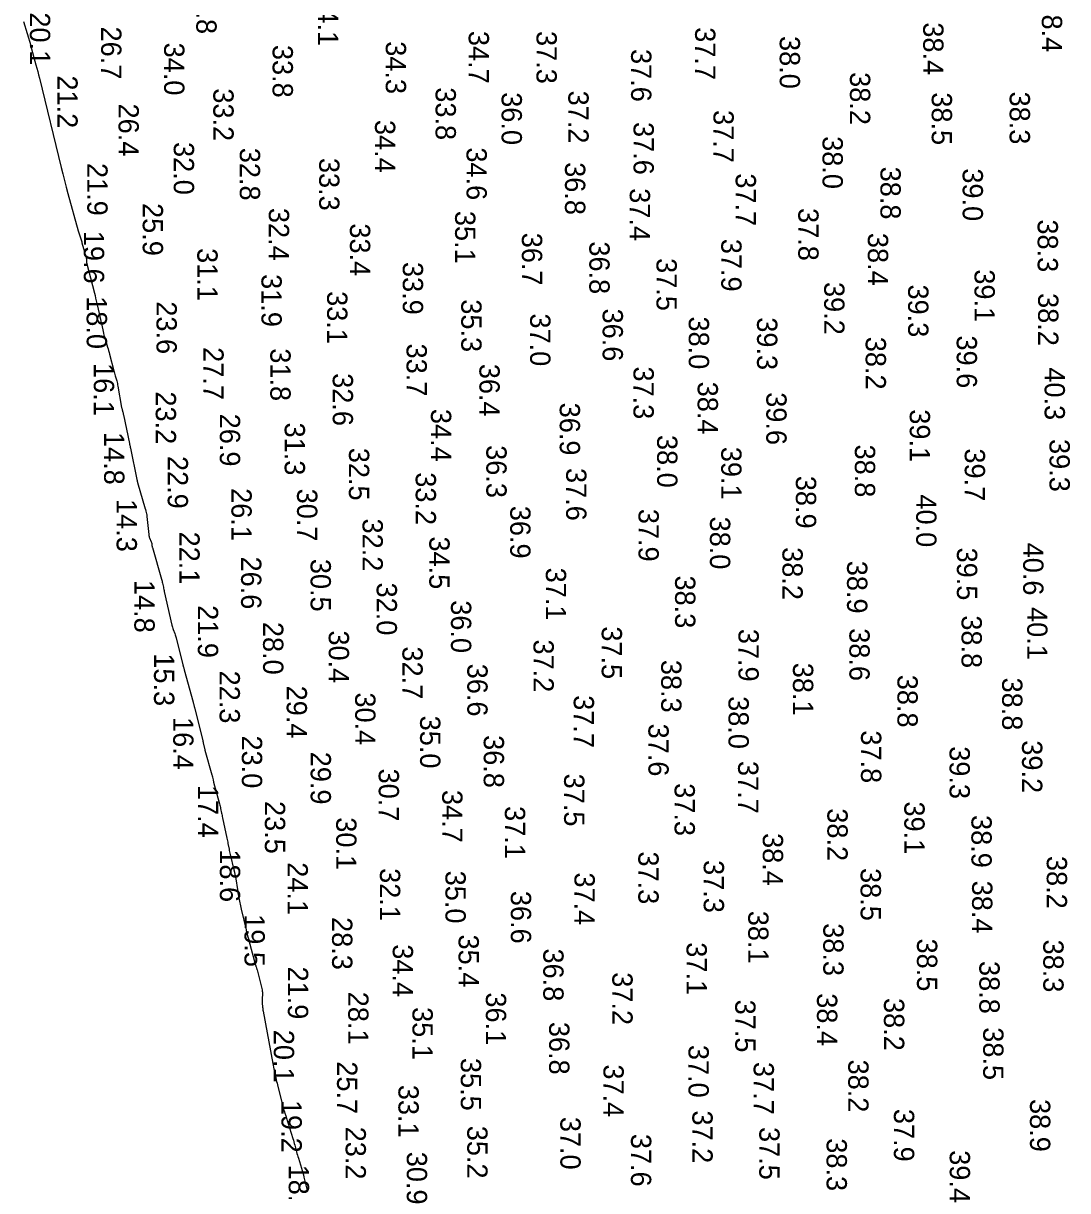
# Model space of a CAD drawing. Extents: x 1178573 to 1187098, y 693282 to 751751.
# Drawn here: x 1180394 to 1181038, y 701736 to 702455 of the extents above; entities that cross this region are included whole.
import ezdxf

# ---------------------------------------------------------------- set-up
doc = ezdxf.new("R2010")
doc.units = 0
doc.layers.add('V-HYDS-MINR', color=7, linetype='Continuous')
doc.layers.add('V-HYDS-SOUN', color=7, linetype='Continuous')

msp = doc.modelspace()

# ---------------------------------------------------------------- linework, layer by layer
at = {"layer": 'V-HYDS-MINR'}
msp.add_lwpolyline([(1180394.31, 702455.91), (1180398.97, 702440.99), (1180398.99, 702440.92), (1180398.99, 702440.89), (1180398.96, 702440.9), (1180398.91, 702440.95), (1180398.68, 702441.24), (1180398.63, 702441.29), (1180398.61, 702441.31), (1180398.6, 702441.28), (1180398.62, 702441.21), (1180402.02, 702429.11), (1180402.59, 702427.06), (1180403.14, 702425), (1180403.67, 702422.95), (1180404.18, 702420.88), (1180417.59, 702365.99), (1180418.6, 702361.93), (1180419.63, 702357.88), (1180420.7, 702353.84), (1180421.79, 702349.81), (1180428.09, 702326.87), (1180428.26, 702326.25), (1180428.45, 702325.64), (1180428.64, 702325.03), (1180428.85, 702324.42), (1180429.69, 702322), (1180429.89, 702321.39), (1180430.08, 702320.78), (1180430.26, 702320.17), (1180430.43, 702319.55), (1180431.9, 702313.95), (1180432, 702313.56), (1180432.12, 702313.17), (1180432.24, 702312.79), (1180432.36, 702312.4), (1180432.96, 702310.62), (1180433.04, 702310.36), (1180433.1, 702310.09), (1180433.13, 702309.82), (1180433.15, 702309.55), (1180433.17, 702308.44), (1180433.18, 702308.17), (1180433.21, 702307.89), (1180433.25, 702307.62), (1180433.31, 702307.36), (1180438.05, 702288.6), (1180438.45, 702287), (1180438.84, 702285.39), (1180439.22, 702283.77), (1180439.6, 702282.16), (1180441.19, 702275.19), (1180441.5, 702273.83), (1180441.8, 702272.47), (1180442.1, 702271.11), (1180442.39, 702269.75), (1180443.68, 702263.76), (1180443.93, 702262.68), (1180444.21, 702261.6), (1180444.51, 702260.52), (1180444.84, 702259.46), (1180446.21, 702255.21), (1180446.54, 702254.15), (1180446.86, 702253.08), (1180447.16, 702252), (1180447.44, 702250.92), (1180450.04, 702240.74), (1180450.25, 702239.95), (1180450.46, 702239.15), (1180450.68, 702238.36), (1180450.9, 702237.56), (1180451.81, 702234.4), (1180452.03, 702233.6), (1180452.22, 702232.8), (1180452.4, 702232), (1180452.55, 702231.19), (1180454.84, 702218.13), (1180454.91, 702217.75), (1180455, 702217.37), (1180455.09, 702216.99), (1180455.18, 702216.61), (1180455.6, 702215.1), (1180455.7, 702214.72), (1180455.79, 702214.34), (1180455.88, 702213.96), (1180455.96, 702213.58), (1180459.65, 702195.8), (1180459.7, 702195.56), (1180459.75, 702195.33), (1180459.81, 702195.09), (1180459.86, 702194.86), (1180460.08, 702193.92), (1180460.13, 702193.69), (1180460.19, 702193.45), (1180460.24, 702193.21), (1180460.29, 702192.98), (1180464.26, 702173.6), (1180464.3, 702173.44), (1180464.33, 702173.29), (1180464.36, 702173.14), (1180464.39, 702172.99), (1180464.52, 702172.38), (1180464.55, 702172.23), (1180464.58, 702172.08), (1180464.62, 702171.93), (1180464.67, 702171.78), (1180469.36, 702155.73), (1180469.48, 702155.32), (1180469.59, 702154.92), (1180469.7, 702154.52), (1180469.8, 702154.11), (1180470.2, 702152.49), (1180470.3, 702152.08), (1180470.37, 702151.67), (1180470.44, 702151.26), (1180470.48, 702150.85), (1180471.55, 702139.72), (1180471.62, 702139.19), (1180471.73, 702138.67), (1180471.88, 702138.16), (1180472.07, 702137.66), (1180473.1, 702135.24), (1180473.2, 702134.97), (1180473.29, 702134.68), (1180473.36, 702134.4), (1180473.4, 702134.1), (1180473.55, 702132.92), (1180473.6, 702132.62), (1180473.65, 702132.33), (1180473.72, 702132.04), (1180473.79, 702131.75), (1180479.43, 702112.21), (1180479.6, 702111.6), (1180479.76, 702110.99), (1180479.91, 702110.37), (1180480.05, 702109.75), (1180480.57, 702107.27), (1180480.71, 702106.65), (1180480.84, 702106.03), (1180480.98, 702105.41), (1180481.12, 702104.79), (1180485.85, 702083.96), (1180486.01, 702083.29), (1180486.19, 702082.63), (1180486.4, 702081.97), (1180486.63, 702081.33), (1180487.59, 702078.75), (1180487.82, 702078.1), (1180488.04, 702077.45), (1180488.23, 702076.79), (1180488.41, 702076.12), (1180492.24, 702061.14), (1180492.34, 702060.74), (1180492.44, 702060.35), (1180492.54, 702059.96), (1180492.64, 702059.56), (1180493.03, 702057.98), (1180493.13, 702057.59), (1180493.23, 702057.2), (1180493.33, 702056.8), (1180493.44, 702056.41), (1180498.89, 702036.47), (1180498.99, 702036.13), (1180499.08, 702035.78), (1180499.17, 702035.43), (1180499.27, 702035.09), (1180499.64, 702033.7), (1180499.73, 702033.36), (1180499.82, 702033.01), (1180499.91, 702032.66), (1180500, 702032.31), (1180504.81, 702012.9), (1180504.84, 702012.77), (1180504.87, 702012.65), (1180504.89, 702012.52), (1180504.92, 702012.4), (1180505.03, 702011.9), (1180505.05, 702011.77), (1180505.08, 702011.65), (1180505.11, 702011.52), (1180505.14, 702011.4), (1180505.73, 702008.87), (1180505.84, 702008.41), (1180505.96, 702007.95), (1180506.08, 702007.49), (1180506.21, 702007.03), (1180510.51, 701991.77), (1180510.62, 701991.39), (1180510.71, 701991), (1180510.8, 701990.62), (1180510.88, 701990.23), (1180511.18, 701988.67), (1180511.26, 701988.29), (1180511.35, 701987.9), (1180511.44, 701987.51), (1180511.54, 701987.13), (1180515.18, 701973.83), (1180515.37, 701973.13), (1180515.54, 701972.42), (1180515.7, 701971.71), (1180515.85, 701971), (1180516.44, 701968.15), (1180516.58, 701967.43), (1180516.73, 701966.72), (1180516.88, 701966.01), (1180517.03, 701965.3), (1180519.7, 701952.81), (1180519.88, 701951.96), (1180520.05, 701951.11), (1180520.21, 701950.26), (1180520.37, 701949.41), (1180521, 701945.99), (1180521.17, 701945.14), (1180521.34, 701944.29), (1180521.53, 701943.44), (1180521.73, 701942.6), (1180524.01, 701933.22), (1180524.34, 701931.82), (1180524.64, 701930.41), (1180524.91, 701929), (1180525.15, 701927.58), (1180526.2, 701921.09), (1180526.36, 701920.07), (1180526.54, 701919.05), (1180526.72, 701918.04), (1180526.9, 701917.03), (1180527.66, 701912.97), (1180527.86, 701911.96), (1180528.07, 701910.95), (1180528.29, 701909.95), (1180528.52, 701908.94), (1180531.52, 701896.33), (1180531.66, 701895.78), (1180531.8, 701895.23), (1180531.94, 701894.68), (1180532.08, 701894.13), (1180532.67, 701891.94), (1180532.82, 701891.39), (1180532.97, 701890.84), (1180533.12, 701890.29), (1180533.26, 701889.75), (1180537.38, 701874.42), (1180537.45, 701874.18), (1180537.52, 701873.95), (1180537.6, 701873.71), (1180537.68, 701873.48), (1180538.02, 701872.55), (1180538.1, 701872.32), (1180538.17, 701872.08), (1180538.24, 701871.85), (1180538.3, 701871.61), (1180541.35, 701859.21), (1180541.49, 701858.56), (1180541.58, 701857.9), (1180541.62, 701857.24), (1180541.61, 701856.58), (1180541.48, 701853.89), (1180541.45, 701853.24), (1180541.45, 701852.58), (1180541.47, 701851.93), (1180541.51, 701851.27), (1180541.7, 701848.65), (1180541.75, 701848), (1180541.83, 701847.35), (1180541.92, 701846.7), (1180542.03, 701846.06), (1180548.06, 701813.88), (1180548.27, 701812.77), (1180548.48, 701811.67), (1180548.7, 701810.57), (1180548.93, 701809.47), (1180549.84, 701805.06), (1180550.07, 701803.97), (1180550.32, 701802.87), (1180550.57, 701801.78), (1180550.84, 701800.68), (1180554.37, 701786.68), (1180554.5, 701786.18), (1180554.64, 701785.68), (1180554.8, 701785.19), (1180554.96, 701784.69), (1180555.63, 701782.73), (1180555.8, 701782.24), (1180555.96, 701781.75), (1180556.12, 701781.25), (1180556.28, 701780.76), (1180560.33, 701767.7), (1180560.64, 701766.69), (1180560.93, 701765.68), (1180561.22, 701764.66), (1180561.49, 701763.64), (1180562.57, 701759.56), (1180562.85, 701758.54), (1180563.13, 701757.52), (1180563.43, 701756.51), (1180563.74, 701755.5), (1180565.65, 701749.36), (1180566.07, 701748), (1180566.45, 701746.63), (1180566.82, 701745.25), (1180567.16, 701743.87), (1180568.94, 701736.38), (1180569.16, 701735.41)], dxfattribs=at)

# ---------------------------------------------------------------- texts
at = {"layer": 'V-HYDS-SOUN'}
for s, p in [('33.8 ', (1180500.86, 702480.66)), ('34.1 ', (1180575.8, 702473.27)), ('38.4 ', (1181021.75, 702469.45)), ('20.1 ', (1180398.34, 702461.49)), ('26.7 ', (1180442.22, 702452.77)), ('34.7 ', (1180668.66, 702450.08)), ('37.3 ', (1180710.43, 702450.02)), ('37.7 ', (1180808.13, 702452.38)), ('38.4 ', (1180948.65, 702455.37)), ('34.0 ', (1180481.03, 702442.87)), ('34.3 ', (1180617.58, 702443.72)), ('38.0 ', (1180860.26, 702446.94)), ('33.8 ', (1180547.87, 702441.45)), ('37.6 ', (1180768.7, 702438.93)), ('21.2 ', (1180415.24, 702422.65)), ('38.2 ', (1180903.53, 702424.69)), ('33.2 ', (1180511.34, 702414.71)), ('33.8 ', (1180648.27, 702415.34)), ('36.0 ', (1180688.94, 702412.3)), ('37.2 ', (1180730.04, 702413.3)), ('38.5 ', (1180953.91, 702412.23)), ('38.3 ', (1181001.93, 702412.71)), ('26.4 ', (1180452.95, 702405.34)), ('37.7 ', (1180819.45, 702401.33)), ('34.4 ', (1180610.92, 702395.24)), ('37.6 ', (1180770.21, 702393.95)), ('38.0 ', (1180886.64, 702385.23)), ('32.0 ', (1180486.97, 702381.62)), ('32.8 ', (1180527.66, 702378.07)), ('34.6 ', (1180667.32, 702378.33)), ('33.3 ', (1180576.54, 702371.83)), ('21.9 ', (1180433.7, 702368.72)), ('36.8 ', (1180727.99, 702369.21)), ('38.8 ', (1180922.31, 702366.45)), ('39.0 ', (1180972.96, 702365.41)), ('37.7 ', (1180833.13, 702362.32)), ('37.4 ', (1180767.88, 702353.18)), ('25.9 ', (1180467.85, 702344.01)), ('32.4 ', (1180545.53, 702341.04)), ('35.1 ', (1180660.28, 702339.21)), ('37.8 ', (1180871.69, 702340.96)), ('33.4 ', (1180595.5, 702331.52)), ('38.3 ', (1181019.16, 702333.94)), ('19.6 ', (1180431.59, 702326.89)), ('36.7 ', (1180701.44, 702325.74)), ('36.8 ', (1180742.98, 702320.42)), ('37.9 ', (1180824.25, 702322)), ('38.4 ', (1180914.56, 702325.65)), ('31.1 ', (1180501.48, 702316.28)), ('33.9 ', (1180628.06, 702307.73)), ('37.5 ', (1180784.36, 702310.1)), ('31.9 ', (1180540.98, 702300.25)), ('39.1 ', (1180980.26, 702303.19)), ('39.2 ', (1180887.65, 702295.39)), ('39.3 ', (1180939.37, 702293.85)), ('18.0 ', (1180433.33, 702286.64)), ('33.1 ', (1180581.44, 702289.77)), ('35.3 ', (1180664.07, 702284.73)), ('38.2 ', (1181019.44, 702288.56)), ('23.6 ', (1180476.34, 702283.48)), ('36.6 ', (1180751.18, 702279.02)), ('37.0 ', (1180706.52, 702276.01)), ('38.0 ', (1180804.23, 702274.14)), ('39.3 ', (1180846.29, 702273.64)), ('33.7 ', (1180630.38, 702257.46)), ('38.2 ', (1180913.21, 702261.63)), ('39.6 ', (1180969.29, 702262.45)), ('27.7 ', (1180505.18, 702255.27)), ('31.8 ', (1180546.46, 702254.54)), ('16.1 ', (1180437.71, 702245.45)), ('36.4 ', (1180675.26, 702244.97)), ('37.3 ', (1180770.17, 702243.36)), ('40.3 ', (1181023.45, 702242.8)), ('32.6 ', (1180584.9, 702239.22)), ('23.2 ', (1180475.87, 702227.97)), ('38.4 ', (1180809.71, 702233.98)), ('39.6 ', (1180852, 702227.48)), ('36.9 ', (1180724.74, 702221.05)), ('26.9 ', (1180515.36, 702214.25)), ('34.4 ', (1180645.4, 702217.22)), ('39.1 ', (1180940.36, 702216.97)), ('31.3 ', (1180555.31, 702208.78)), ('14.8 ', (1180444.07, 702203)), ('38.0 ', (1180784.74, 702201.14)), ('39.3 ', (1181026.47, 702198.64)), ('32.5 ', (1180594.89, 702193.24)), ('36.3 ', (1180679.52, 702194.87)), ('39.1 ', (1180824.22, 702193.84)), ('38.8 ', (1180906.57, 702195.23)), ('39.7 ', (1180974.24, 702192.86)), ('22.9 ', (1180483.24, 702188.21)), ('33.2 ', (1180636.01, 702178.16)), ('37.6 ', (1180728.7, 702180.79)), ('38.9 ', (1180870.22, 702175.97)), ('26.1 ', (1180522.48, 702168.38)), ('30.7 ', (1180562.92, 702168.06)), ('40.0 ', (1180944.32, 702164.5)), ('14.3 ', (1180451.77, 702161.66)), ('36.9 ', (1180694.23, 702157.5)), ('37.9 ', (1180773.27, 702155.63)), ('32.2 ', (1180603.27, 702149.65)), ('38.0 ', (1180817.29, 702150.85)), ('22.1 ', (1180490.4, 702141.61)), ('34.5 ', (1180644.4, 702138.61)), ('40.6 ', (1181010.23, 702134.79)), ('38.2 ', (1180861.93, 702132.03)), ('39.5 ', (1180969.43, 702131.76)), ('26.6 ', (1180528.44, 702126.23)), ('30.5 ', (1180571.27, 702124.8)), ('37.1 ', (1180716.18, 702119.4)), ('38.9 ', (1180901.74, 702123.64)), ('38.3 ', (1180795.8, 702114.55)), ('14.8 ', (1180462.7, 702111.83)), ('32.0 ', (1180611.97, 702110.2)), ('36.0 ', (1180657.74, 702099.3)), ('21.9 ', (1180501.84, 702096.28)), ('40.1 ', (1181012.7, 702095.12)), ('28.0 ', (1180541.99, 702085.98)), ('37.5 ', (1180750.6, 702083.23)), ('38.8 ', (1180972.28, 702090.01)), ('30.4 ', (1180582.44, 702080.7)), ('37.9 ', (1180834.85, 702081.71)), ('38.6 ', (1180903.18, 702082.07)), ('32.7 ', (1180627.82, 702070.85)), ('37.2 ', (1180708.58, 702075.15)), ('15.3 ', (1180474.8, 702066.62)), ('38.3 ', (1180787.23, 702062.58)), ('22.3 ', (1180515.22, 702055.96)), ('36.6 ', (1180667.81, 702060.22)), ('38.1 ', (1180868.41, 702060.8)), ('38.8 ', (1180932.78, 702053.4)), ('38.8 ', (1180997.28, 702051.66)), ('29.4 ', (1180556.52, 702046.71)), ('30.4 ', (1180598.72, 702042.51)), ('37.7 ', (1180733.36, 702040.83)), ('38.0 ', (1180828.7, 702040.22)), ('16.4 ', (1180486.61, 702027.36)), ('35.0 ', (1180638.71, 702028.21)), ('37.6 ', (1180779.36, 702023.31)), ('37.8 ', (1180910.34, 702019.14)), ('23.0 ', (1180528.93, 702015.97)), ('36.8 ', (1180677.93, 702016.22)), ('39.2 ', (1181009.53, 702013.01)), ('29.9 ', (1180571.3, 702005.99)), ('39.3 ', (1180964.89, 702009.37)), ('37.7 ', (1180834.61, 702000.31)), ('30.7 ', (1180613.22, 701995.59)), ('37.5 ', (1180727.43, 701992.48)), ('17.4 ', (1180501.83, 701985.53)), ('34.7 ', (1180652.33, 701982.43)), ('37.3 ', (1180795.5, 701986.6)), ('23.5 ', (1180543.12, 701975.62)), ('39.1 ', (1180937.02, 701975.34)), ('37.1 ', (1180690.95, 701972.52)), ('38.2 ', (1180889.62, 701971.14)), ('30.1 ', (1180587.02, 701965.59)), ('38.9 ', (1180978.35, 701966.98)), ('38.4 ', (1180849.83, 701955.87)), ('18.6 ', (1180515.38, 701945.85)), ('37.3 ', (1180773.16, 701944.54)), ('37.3 ', (1180813.45, 701939.22)), ('38.2 ', (1181024.76, 701941.78)), ('24.1 ', (1180557.09, 701937.9)), ('32.1 ', (1180613.98, 701934.26)), ('35.0 ', (1180654.33, 701932.7)), ('38.5 ', (1180910.11, 701934.31)), ('37.4 ', (1180733.82, 701931.62)), ('38.4 ', (1180978.77, 701926.54)), ('36.6 ', (1180694.62, 701920.26)), ('19.5 ', (1180530.55, 701905.9)), ('28.3 ', (1180584.51, 701904.12)), ('38.1 ', (1180840.85, 701907.98)), ('38.3 ', (1180887.1, 701900.34)), ('35.4 ', (1180662.43, 701893.37)), ('38.5 ', (1180944.82, 701890.88)), ('38.3 ', (1181022.63, 701890.24)), ('34.4 ', (1180621.88, 701887.36)), ('36.8 ', (1180714.61, 701884.76)), ('37.1 ', (1180802.86, 701888.59)), ('38.8 ', (1180983.24, 701877.05)), ('21.9 ', (1180557.29, 701873.64)), ('37.2 ', (1180757.14, 701870.13)), ('28.1 ', (1180594.43, 701858.11)), ('36.1 ', (1180679.24, 701857.72)), ('37.5 ', (1180832.85, 701853.24)), ('38.4 ', (1180883.23, 701857.18)), ('38.2 ', (1180924.49, 701854.25)), ('35.1 ', (1180634.03, 701848.66)), ('36.8 ', (1180718.21, 701839.55)), ('20.1 ', (1180548.6, 701834.66)), ('38.5 ', (1180985.6, 701836.22)), ('37.0 ', (1180804.06, 701825.36)), ('35.5 ', (1180663.79, 701817.32)), ('25.7 ', (1180587.56, 701815.24)), ('37.4 ', (1180751.67, 701813.35)), ('37.7 ', (1180844.19, 701814.85)), ('38.2 ', (1180902.48, 701816.32)), ('33.1 ', (1180625.37, 701800.76)), ('19.2 ', (1180553.33, 701791.45)), ('38.9 ', (1181014.44, 701792.01)), ('37.0 ', (1180725.13, 701781.03)), ('37.2 ', (1180806.45, 701784.99)), ('37.9 ', (1180930.62, 701785.94)), ('23.2 ', (1180592.83, 701774.98)), ('35.2 ', (1180667.77, 701775.54)), ('37.5 ', (1180847.68, 701774.77)), ('37.6 ', (1180768.63, 701770.56)), ('38.3 ', (1180889.14, 701767.83)), ('30.9 ', (1180630.52, 701759.53)), ('39.4 ', (1180964.99, 701760.49)), ('18.5 ', (1180557.81, 701751.61))]:
    msp.add_text(s, height=12.5, rotation=270, dxfattribs=at).set_placement(p)

doc.saveas('drawing.dxf')
